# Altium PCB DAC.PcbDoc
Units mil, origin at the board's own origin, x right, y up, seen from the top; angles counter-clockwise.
Board outline 6520 x 6780 mil, 2 copper layers (Top Layer, Bottom Layer); 122 components, 76 nets, 405 pads, 94 vias.
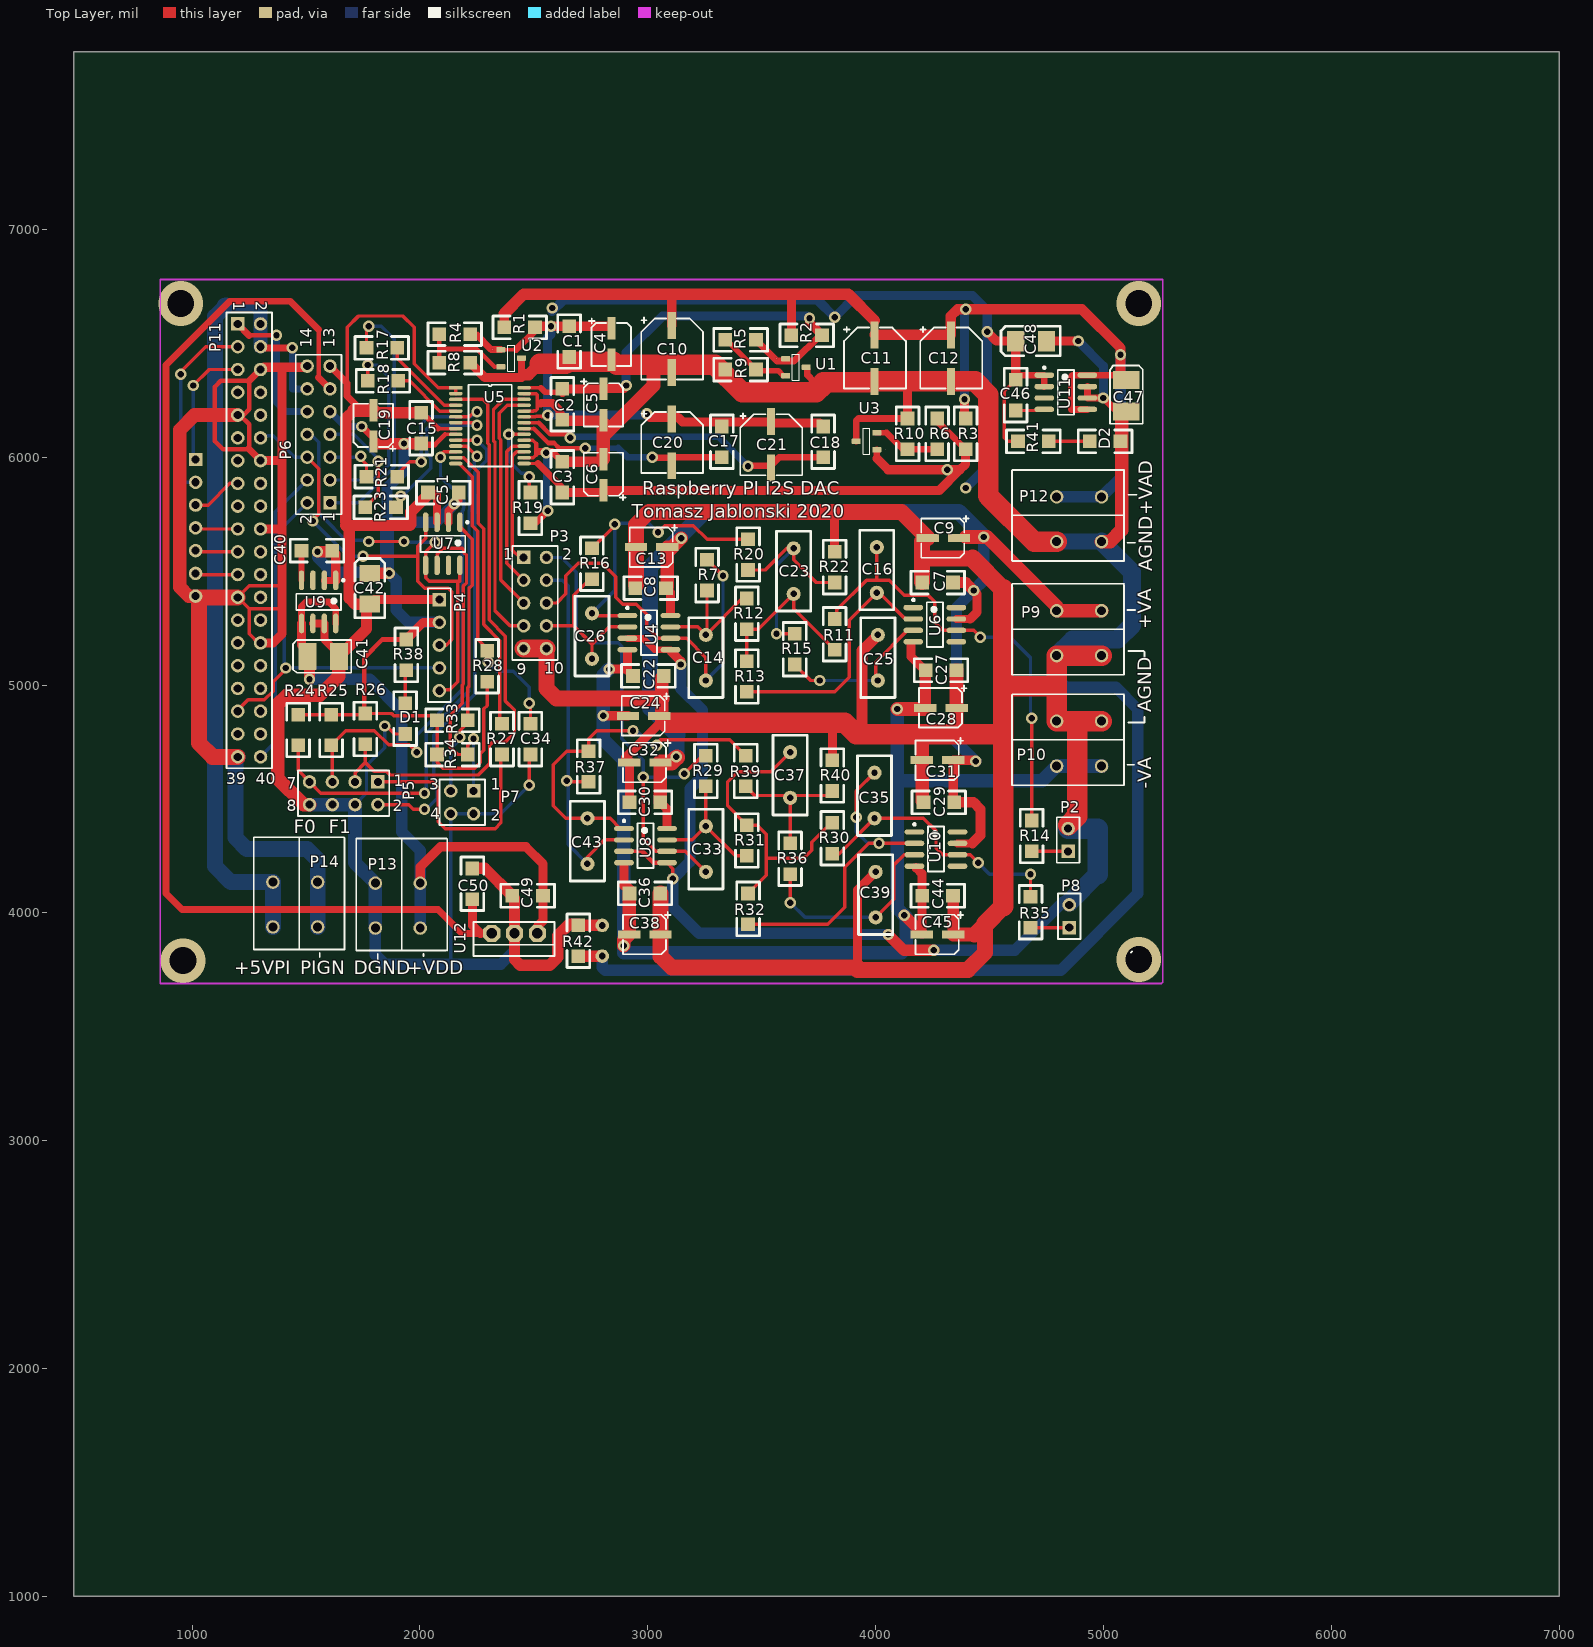
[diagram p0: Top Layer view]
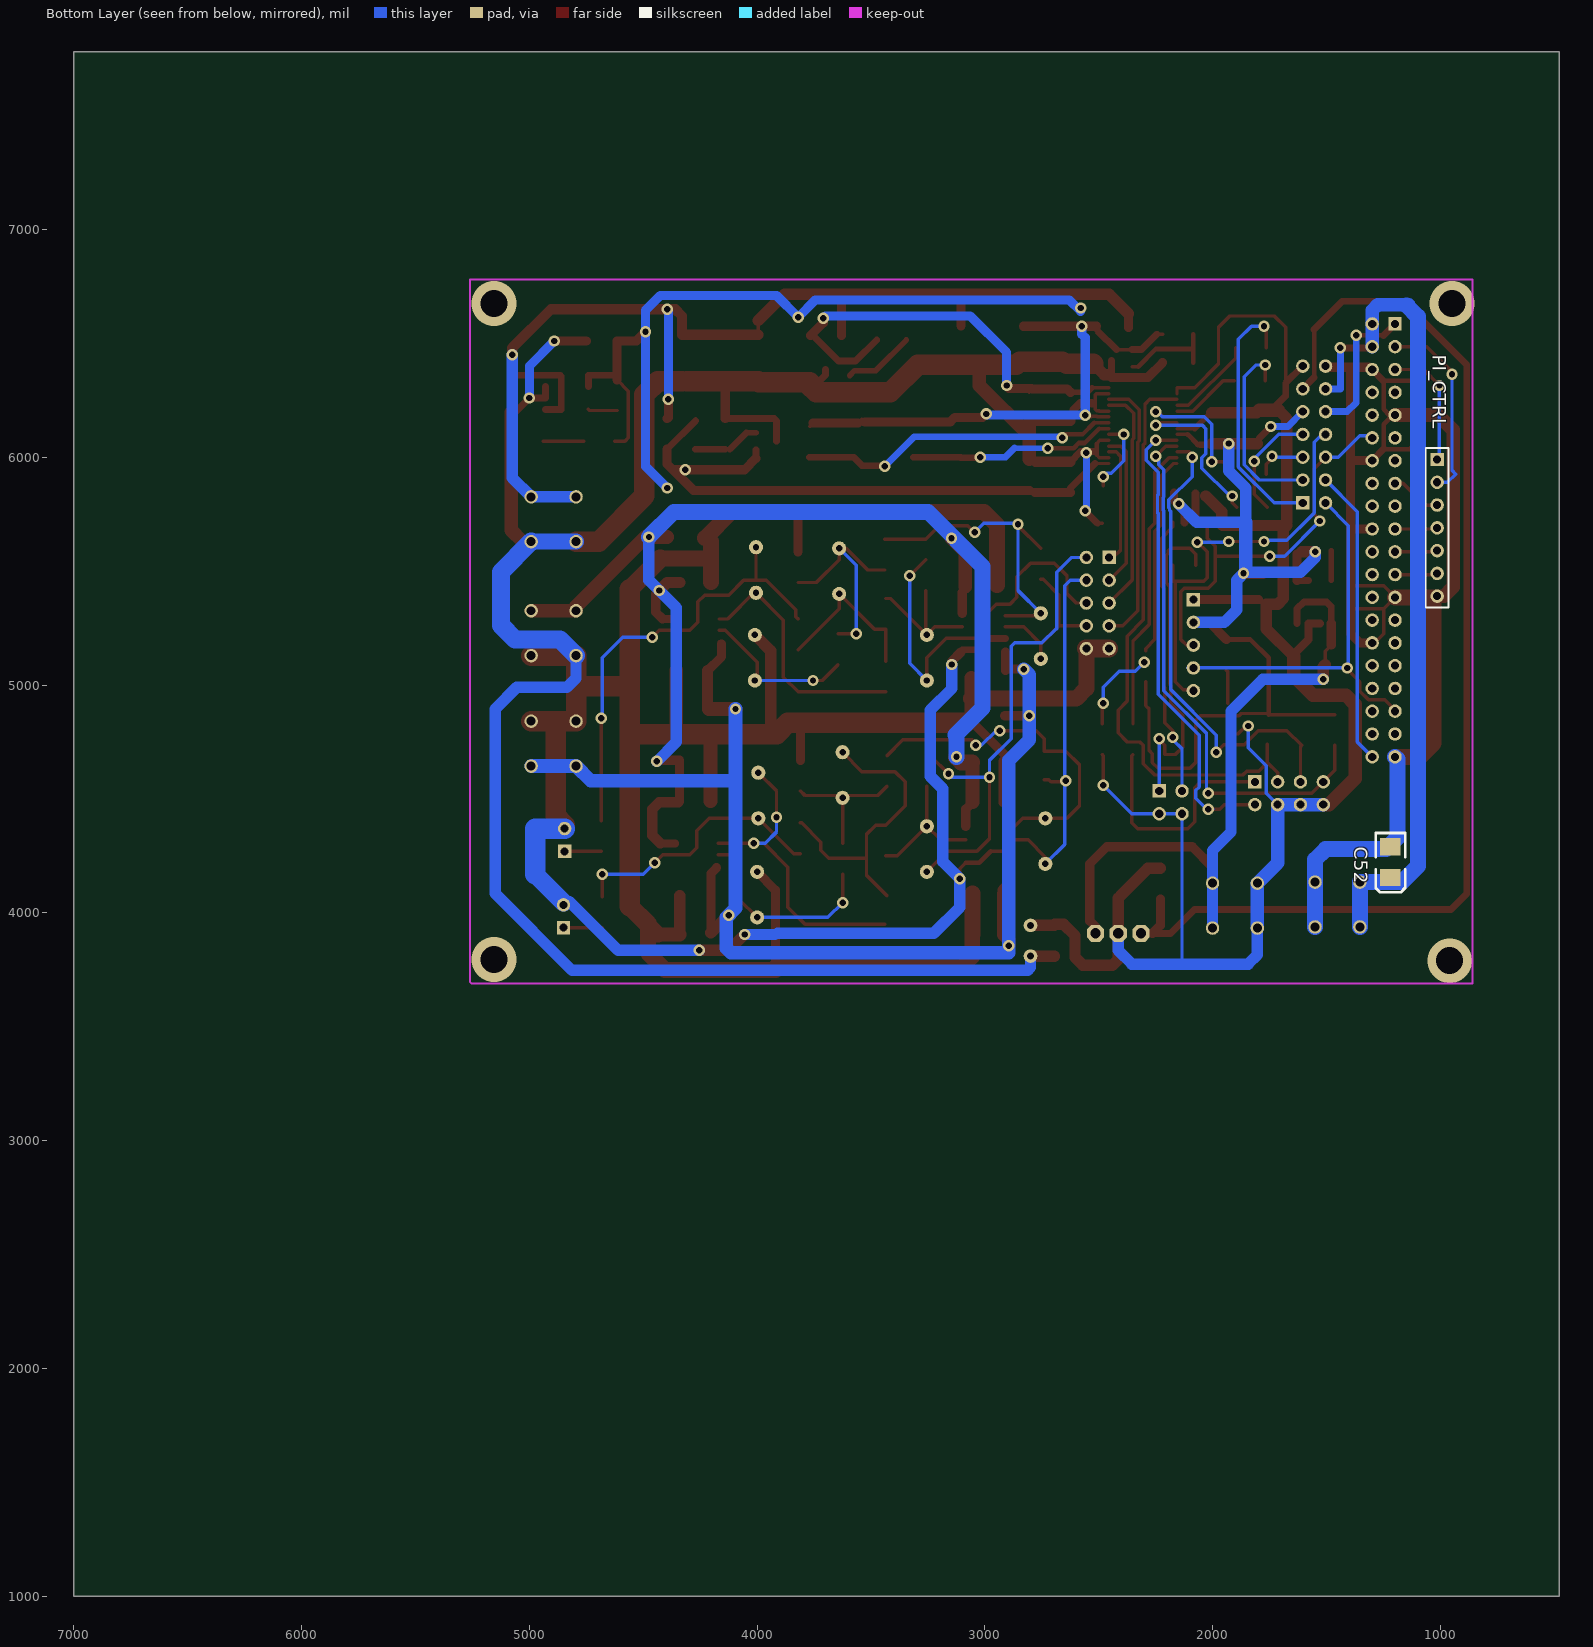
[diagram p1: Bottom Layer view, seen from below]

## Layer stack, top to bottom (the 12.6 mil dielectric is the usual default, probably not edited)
Top Solder: solder mask 0.4, Solder Resist, Dk 3.5
Top Layer: signal copper 1.4
Dielectric 1: dielectric 12.6, FR-4, Dk 4.8
Bottom Layer: signal copper 1.4
Bottom Solder: solder mask 0.4, Solder Resist, Dk 3.5

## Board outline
480,1000 7000,1000 7000,7780 480,7780

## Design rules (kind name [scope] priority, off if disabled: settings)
Clearance [All] p1: gap=10 ignorepadtopadclearanceinfootprint=FALSE except(0: Arc-Hole Track-Hole SMDPad-Hole THPad-Hole Via-Hole Fill-Hole Poly-Hole Region-Hole Text-Hole)
PolygonConnect [All] p1: connectstyle=Relief reliefconductorwidth=10 reliefentries=4 polygonreliefangle="90 Angle" airgapwidth=10
RoutingVias [All] p1: holewidth=28 width=50 viastyle="Through Hole" minholewidth=28 minwidth=50 maxholewidth=28 maxwidth=50
SolderMaskExpansion [All] p1: expansion=4
Width Width_2 [All] p1: maxlimit=15 minlimit=15 preferedwidth=15
Width Width_1 [InNet('PIGND')] p2: maxlimit=80 minlimit=60 preferedwidth=70
Width [InNet('+5VPI')] p3: maxlimit=30 minlimit=30 preferedwidth=30
30 further rules are at their usual default settings.

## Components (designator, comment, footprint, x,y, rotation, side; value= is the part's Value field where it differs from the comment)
C1 "" 1206 2655,6575 r270 top
C2 "" 1206 2625,6300 r270 top
C3 "" 1206 2625,5845 r90 top
C4 "" 10uf/25v 2840,6495 r90 top
C5 "" 10uf/25v 2805,6230 r90 top
C6 "" 10uf/25v 2805,5925 r270 top
C7 "" 1206 4340,5450 r180 top
C8 "" 1206 3080,5425 r180 top
C9 "" 10uf/25v 4295,5645 r0 top
C10 "47u" 47u/25v 3105,6475 r90 top
C11 "47u" 47u/25v 3995,6435 r90 top
C12 "47u" 47u/25v 4330,6435 r90 top
C13 "" 10uf/25v 3015,5605 r0 top
C14 "" RAD0.2 3255,5020 r90 top
C15 "" 1206 2005,6060 r90 top
C16 "" RAD0.2 4005,5405 r90 top
C17 "" 1206 3325,6135 r270 top
C18 "" 1206 3770,6135 r270 top
C19 "" 10uf/25v 1795,6140 r270 top
C20 "47u" 47u/25v 3105,6065 r90 top
C21 "47u" 47u/25v 3540,6055 r90 top
C22 "" 1206 2935,5040 r0 top
C23 "" RAD0.2 3640,5400 r90 top
C24 "" 10uf/25v 2980,4865 r0 top
C25 "" RAD0.2 4010,5020 r90 top
C26 "" RAD0.2 2755,5115 r90 top
C27 "" 1206 4220,5065 r0 top
C28 "" 10uf/25v 4285,4900 r0 top
C29 "" 1206 4345,4485 r180 top
C30 "" 1206 3055,4485 r180 top
C31 "" 10uf/25v 4270,4670 r0 top
C32 "" 10uf/25v 2985,4660 r0 top
C33 "" RAD0.2 3255,4180 r90 top
C34 "" 1206 2485,4830 r270 top
C35 "" RAD0.2 3995,4615 r270 top
C36 "" 1206 2920,4085 r0 top
C37 "" RAD0.2 3625,4705 r270 top
C38 "" 10uf/25v 2985,3905 r0 top
C39 "" RAD0.2 4000,3980 r90 top
C40 "10n" 1206 1615,5590 r180 top
C41 "1uF" 10uSMD 1575,5125 r180 top
C42 "10uF" 3528 1780,5490 r90 top
C43 "" RAD0.2 2735,4215 r90 top
C44 "" 1206 4205,4075 r0 top
C45 "" 10uf/25v 4270,3905 r0 top
C46 "10n" 1206 4615,6340 r270 top
C47 "1uF" 10uSMD 5100,6270 r90 top
C48 "1uF" 3528 4615,6510 r180 top
C49 "" 1206 2540,4075 r180 top
C50 "" 1206 2230,4060 r90 top
C51 "" 1206 2170,5845 r180 top
C52 "10uF" 3528 1220,4155 r270 bottom
D1 "LED0" 1206 1935,4920 r270 top
D2 "LED0" 1206 4940,6070 r0 top
P2 "CH_L" HDR1X2 4845,4270 r90 top
P3 "FLT_ANALOG" HDR2X5 2455,5560 r270 top
P4 "MCLK_MUL" HDR1X5 2085,5375 r270 top
P5 "Header 4X2" HDR2X4 1815,4575 r180 top
P6 "I2S_ISOL" HDR2X7 1605,5800 r90 top
P7 "MCLK SET" HDR2X2 2235,4535 r180 top
P8 "CH_R" HDR1X2 4850,3935 r90 top
P9 "" wago 4795,5145 r0 top
P10 "" wago 4795,4660 r0 top
P11 "PI_connect" HDR2X20 1200,6585 r270 top
P12 "" wago 4795,5645 r0 top
P13 "" wago 1820,4130 r270 top
P14 "" wago 1370,4135 r270 top
PI_CTRL "" HDR1X7 1015,5990 r270 bottom
R1 "" 1206 2370,6570 r0 top
R2 "" 1206 3630,6535 r0 top
R3 "" 1206 4395,6170 r270 top
R4 "" 1206 2220,6540 r180 top
R5 "" 1206 3475,6515 r180 top
R6 "" 1206 4270,6170 r270 top
R7 "" 1206 3260,5415 r90 top
R8 "" 1206 2085,6415 r0 top
R9 "" 1206 3475,6385 r180 top
R10 "" 1206 4140,6035 r90 top
R11 "" 1206 3820,5290 r270 top
R12 "" 1206 3435,5245 r90 top
R13 "" 1206 3435,4970 r90 top
R14 "" 1206 4685,4270 r90 top
R15 "" 1206 3645,5090 r90 top
R16 "" 1206 2755,5600 r270 top
R17 "" 1206 1765,6480 r0 top
R18 "" 1206 1770,6335 r0 top
R19 "" 1206 2485,5710 r90 top
R20 "" 1206 3440,5505 r90 top
R21 "" 1206 1765,5915 r0 top
R22 "" 1206 3820,5585 r270 top
R23 "" 1206 1760,5780 r0 top
R24 "" 1206 1465,4870 r270 top
R25 "" 1206 1610,4870 r270 top
R26 "" 1206 1760,4875 r270 top
R27 "" 1206 2360,4830 r270 top
R28 "" 1206 2295,5015 r90 top
R29 "" 1206 3255,4555 r90 top
R30 "" 1206 3810,4260 r90 top
R31 "" 1206 3435,4385 r270 top
R32 "" 1206 3440,3950 r90 top
R33 "" 1206 2075,4845 r0 top
R34 "" 1206 2075,4695 r0 top
R35 "" 1206 4680,3935 r90 top
R36 "" 1206 3625,4170 r90 top
R37 "" 1206 2740,4710 r270 top
R38 "" 1206 1940,5200 r270 top
R39 "" 1206 3430,4555 r90 top
R40 "" 1206 3810,4670 r270 top
R41 "" 1206 4625,6070 r0 top
R42 "" 1206 2695,3810 r90 top
U1 "TL431" SOT23-3 3650,6395 r0 top
U2 "TL431" SOT23-3 2400,6435 r0 top
U3 "TL431" SOt23-3 3960,6070 r180 top
U4 "OPA1612AID" TI-D8_N 3005,5230 r0 top
U5 "PCM1794A" pcm1796 2150,6305 r0 top
U6 "OPA1611AID" TI-D8_N 4260,5265 r0 top
U7 "ICS570B" TI-D8_n 2100,5620 r270 top
U8 "OPA1612AID" TI-D8_N 2990,4295 r0 top
U9 "3V3" TI-D8_N 1555,5365 r270 top
U10 "OPA1611AID" TI-D8_N 4265,4280 r0 top
U11 "5V0" TI-D8_n 4835,6285 r0 top
U12 "7805" 78XXST 2490,3895 r180 top

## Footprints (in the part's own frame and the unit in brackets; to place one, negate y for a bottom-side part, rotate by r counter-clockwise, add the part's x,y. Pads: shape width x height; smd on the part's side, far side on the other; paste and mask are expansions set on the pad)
10uf/25v [mm]
  rect 2.5x0.9 smd: 1(1.8,0) 2(-1.7,0)
  silkscreen extent -2.4,-2.2 2.9,2.5
10uSMD [mm]
  rect 2x3 smd: 1(1.75,0) 2(-1.75,0)
  silkscreen extent -3.12,-1.85 3.35,1.8
47u/25v [mm]
  rect 3x0.9 smd: 1(2.6,0) 2(-2.6,0)
  silkscreen extent -3.4,-3.5 3.5,3.4
78XXST [mil]
  oct 75x75 hole 45: 1(-25,-15) 2(75,-15) 3(175,-15)
  silkscreen extent -100,-65 255,85
1206 [mil]
  rect 60x60 smd: 1(0,0) 2(135,0)
  silkscreen extent -50,-50 185,50
3528 [mil]
  rect 75x90 smd: 1(0,0) 2(-135,0)
  silkscreen extent -195,-65 65,65
HDR1X2 [mm] "Connector; Header; 2 Position"
  rect 1.5x1.5 hole 0.9: 1(0,0)
  round 1.5 hole 0.9: 2(2.54,0)
  silkscreen extent -1.27,-1.27 3.81,1.27
HDR1X5 [mm] "Connector; Header; 5 Position"
  rect 1.5x1.5 hole 0.9: 1(0,0)
  round 1.5 hole 0.9: 2(2.54,0) 3(5.08,0) 4(7.62,0) 5(10.16,0)
  silkscreen extent -1.27,-1.27 11.43,1.27
HDR1X7 [mm] "Connector; Header; 7 Position"
  rect 1.5x1.5 hole 0.9: 1(0,0)
  round 1.5 hole 0.9: 2(2.54,0) 3(5.08,0) 4(7.62,0) 5(10.16,0) 6(12.7,0) 7(15.24,0)
  silkscreen extent -1.27,-1.27 16.51,1.27
HDR2X2 [mm] "Connector; Header; 2x2 Position"
  rect 1.5x1.5 hole 0.9: 1(0,0)
  round 1.5 hole 0.9: 2(0,2.54) 3(2.54,0) 4(2.54,2.54)
  silkscreen extent -1.27,-1.27 3.81,3.81
HDR2X4 [mm] "Connector; Header; 4x2 Position"
  rect 1.5x1.5 hole 0.9: 1(0,0)
  round 1.5 hole 0.9: 2(0,2.54) 3(2.54,0) 4(2.54,2.54) 5(5.08,0) 6(5.08,2.54) 7(7.62,0) 8(7.62,2.54)
  silkscreen extent -1.27,-1.27 8.89,3.81
HDR2X5 [mm] "Connector; Header; 5x2 Position"
  rect 1.5x1.5 hole 0.9: 1(0,0)
  round 1.5 hole 0.9: 2(0,2.54) 3(2.54,0) 4(2.54,2.54) 5(5.08,0) 6(5.08,2.54) 7(7.62,0) 8(7.62,2.54) 9(10.16,0) 10(10.16,2.54)
  silkscreen extent -1.27,-1.27 11.43,3.81
HDR2X7 [mm] "Connector; Header; 7x2 Position"
  rect 1.5x1.5 hole 0.9: 1(0,0)
  round 1.5 hole 0.9: 2(0,2.54) 3(2.54,0) 4(2.54,2.54) 5(5.08,0) 6(5.08,2.54) 7(7.62,0) 8(7.62,2.54) 9(10.16,0) 10(10.16,2.54) 11(12.7,0) 12(12.7,2.54) 13(15.24,0) 14(15.24,2.54)
  silkscreen extent -1.27,-1.27 16.51,3.81
HDR2X20 [mm] "Connector; Header; 20x2 Position"
  rect 1.5x1.5 hole 0.9: 1(0,0)
  round 1.5 hole 0.9: 2(0,2.54) 3(2.54,0) 4(2.54,2.54) 5(5.08,0) 6(5.08,2.54) 7(7.62,0) 8(7.62,2.54) 9(10.16,0) 10(10.16,2.54) 11(12.7,0) 12(12.7,2.54) 13(15.24,0) 14(15.24,2.54) 15(17.78,0) 16(17.78,2.54) 17(20.32,0) 18(20.32,2.54) 19(22.86,0) 20(22.86,2.54) 21(25.4,0) 22(25.4,2.54) 23(27.94,0) 24(27.94,2.54) 25(30.48,0) 26(30.48,2.54) 27(33.02,0) 28(33.02,2.54) 29(35.56,0) 30(35.56,2.54) 31(38.1,0) 32(38.1,2.54) 33(40.64,0) 34(40.64,2.54) 35(43.18,0) 36(43.18,2.54) 37(45.72,0) 38(45.72,2.54) 39(48.26,0) 40(48.26,2.54)
  silkscreen extent -1.27,-1.27 49.53,3.81
pcm1796 [mm]
  rect 1.5x0.4 smd: 1(0.178,0)
  oval 1.5x0.4 smd: 2(0.178,-0.65) 3(0.178,-1.3) 4(0.178,-1.95) 5(0.178,-2.6) 6(0.178,-3.25) 7(0.178,-3.9) 8(0.178,-4.55) 9(0.178,-5.2) 10(0.178,-5.85) 11(0.178,-6.5) 12(0.178,-7.15) 13(0.178,-7.8) 14(0.178,-8.45) 15(7.797,-8.45) 16(7.797,-7.8) 17(7.797,-7.15) 18(7.797,-6.5) 19(7.797,-5.85) 20(7.797,-5.2) 21(7.797,-4.55) 22(7.797,-3.9) 23(7.797,-3.25) 24(7.797,-2.6) 25(7.797,-1.95) 26(7.797,-1.3) 27(7.797,-0.65) 28(7.797,0)
  silkscreen extent 1.58,-8.78 6.41,0.32
RAD0.2 [mil]
  round 62 hole 28: 1(0,0) 2(200,0)
  silkscreen extent -75,-75 275,75
SOT23-3 [mm] "SOT23, 3 pin"
  round 0.5 on Mech15: 0(0,0)
  rrect25% 1x0.6 smd: 1(-1.15,0.95) 2(-1.15,-0.95) 3(1.15,0)
  silkscreen extent -0.38,-1.45 0.38,1.45, body extent -1.4,-1.45 1.4,1.45, height 1.29
SOt23-3 [mm] "SOT23, 3 pin"
  round 0.5 on Mech15: 0(0,0)
  rrect25% 1x0.6 smd: 1(-1.15,0.95) 2(-1.15,-0.95) 3(1.15,0)
  silkscreen extent -0.38,-1.45 0.38,1.45, body extent -1.4,-1.45 1.4,1.45, height 1.29
TI-D8_N [mm] "SOIC, 8-Leads, Body 4.9x3.9mm, Pitch 1.27mm, IPC Medium Density"
  oval 2.2x0.6 smd: 1(-2.4,1.905) 2(-2.4,0.635) 3(-2.4,-0.635) 4(-2.4,-1.905) 5(2.4,-1.905) 6(2.4,-0.635) 7(2.4,0.635) 8(2.4,1.905)
  silkscreen extent -2.52,-2.5 0.9,2.88, body extent -2,-2.5 2,2.5, height 1.75
TI-D8_n [mm] "SOIC, 8-Leads, Body 5x4mm, Pitch 1.27mm, IPC Medium Density"
  oval 2.2x0.6 smd: 1(-2.4,1.905) 2(-2.4,0.635) 3(-2.4,-0.635) 4(-2.4,-1.905) 5(2.4,-1.905) 6(2.4,-0.635) 7(2.4,0.635) 8(2.4,1.905)
  silkscreen extent -2.52,-2.5 0.9,2.88, body extent -2,-2.5 2,2.5, height 1.75
wago [mm]
  round 1.5 hole 1: 1(0,4.6) 1(5,4.6) 2(0,-0.4) 2(5,-0.4)
  silkscreen extent -5,-2.54 7.5,7.6

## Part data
C1 C2 C3 C7 C8 C14 C15 C16 C17 C18 C22 C23 C25 C26 C27 C29 C30 C33 C34 C35 C36 C37 C39 C43 C44 C49 C50 C51: library part Cap, "Capacitor"
C4 C5 C6 C9 C10 C11 C12 C13 C19 C20 C21 C24 C28 C31 C32 C38 C41 C42 C45 C47 C48 C52: library part ELECTRO2, "Electrolytic Capacitor"
C40 C46: library part CAP, "Capacitor"
D1 D2: "Typical INFRARED GaAs LED"
P2 P8 P9 P10 P12 P13 P14: library part "Header 2", "Header, 2-Pin"
P3: library part "Header 5X2", "Header, 5-Pin, Dual row"
P4: library part "Header 5", "Header, 5-Pin"
P5: "Header, 4-Pin, Dual row"
P6: library part "Header 7X2", "Header, 7-Pin, Dual row"
P7: library part "Header 2X2", "Header, 2-Pin, Dual row"
P11: library part "Header 20X2", "Header, 20-Pin, Dual row"
PI_CTRL: library part "Header 7", "Header, 7-Pin"
R1 R2 R3 R4 R5 R6 R7 R8 R9 R10 R11 R12 R13 R14 R15 R16 R17 R18 R19 R20 R21 R22 R23 R24 R25 R26 R27 R28 R29 R30 R31 R32 R33 R34 R35 R36 R37 R38 R39 R40 R41 R42: library part Res2, "Resistor"
U4 U6 U8 U10: "1.1 nV/rtHz Noise, Low Power, Precision Operational Amplifier, 4.5 to 36 V, -40 to 85 degC, 8-pin SOIC (D8), Green (RoHS & no Sb/Br)"
U7: library part ICS570
U9 U11: library part LT1763
U12: library part 78XX

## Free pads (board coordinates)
  round 60 hole 30: 0(2800,3945) 1(2800,3810)

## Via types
v1: diameter 50, hole 28, Top Layer to Bottom Layer, 90 vias
v2: diameter 196.85, hole 118.11, Top Layer to Bottom Layer, 4 vias

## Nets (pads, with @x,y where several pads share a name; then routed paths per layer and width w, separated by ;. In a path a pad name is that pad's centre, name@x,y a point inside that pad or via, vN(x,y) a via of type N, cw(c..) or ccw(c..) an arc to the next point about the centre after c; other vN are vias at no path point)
+3,3VDD: C15.1 C19.1 C40.1 C42.1 C51.1 P4.2 P6.9 R24.1 R25.1 R26.1 R28.1 R33.1 R34.1 R38.1 U5.9 U7.2 U9.1 U9.2 | length 4840.4
  Top Layer w15: R24.1 R25.1 1755,4870 R26.1 1875,4875 1885,4865 2055,4865 R33.1 R34.1 2075,4660 2100,4635 2240,4635 2264.82,4659.82 2264.82,4699.29 2280,4714.47 2280,4895 2295,4910 R28.1 ; v1@1550,5570 v1(1550,5585) ; C40.1@1610,5585 C40.1 C40.1@1630,5575 ; C19.1@1795,6085 C19.1 C19.1@1804.13,6060 ; C15.1 C15.1@2010,6055 ; 2110.28,6100.27 U5.9
  Top Layer w20: R26.1@1755,4870 1755,5120 1835,5200 R38.1
  Top Layer w22: 2065,6055 2110.28,6100.27
  Top Layer w25: 2055,6055 2065,6055
  Top Layer w30: U9.2 U9.1 ; v1(1745,6135) C19.1@1795,6085 ; C15.1@2010,6055 2055,6055
  Top Layer w35: U7.2 2125,5765 2170,5810 C51.1
  Top Layer w40: U9.1 C40.1@1630,5575 ; R38.1 2015,5275 P4.2
  Top Layer w50: v1(1550,5585) C40.1@1610,5585 ; C42.1 v1(1865,5490) ; C19.1@1804.13,6060 v1(1930,6060) C15.1
  Bottom Layer w30: P6.9 1670,6135 v1(1745,6135)
  Bottom Layer w50: v1(1550,5585) 1550,5560 1615,5495 v1@1845,5495 ; v1@1855,5500 1895,5460 1895,5330 1950,5275 P4.2 ; v1(1930,6060) 1930,5939.44 1855,5864.44 1855,5715 2070,5715 v1(2150,5795)
  Bottom Layer w60: v1@1855,5500 1855,5715
+3,3VPI: P6.10 P11.1 | length 637.3
  Top Layer w20: 1250,6535 v1(1370,6535)
  Top Layer w30: P11.1 1250,6535
  Bottom Layer w30: v1(1370,6535) 1370,6275 1370,6240 1410,6200 P6.10
+5VA: C46.1 C48.1 R41.1 U11.1 U11.2 | length 3684.7
  Top Layer w15: R41.1 4580,6070 4565,6085 4565,6290 C46.1 C46.1@4635,6360
  Top Layer w30: C46.1@4635,6360 U11.1 U11.2
  Top Layer w40: v1(4490,6550) 4530,6510 C48.1 C46.1
  Bottom Layer w40: v1@2580,6640 2630,6690 3745,6690 v1(3820,6615) 3915,6710 4425,6710 4490,6645 v1(4490,6550) 4490,5960 v1(4395,5865)
  other v1: 2580,6655
+5VDD: C50.1 P6.11 U12.3 | length 5105.5
  Top Layer w15: 2265,3910 U12.3
  Top Layer w20: 1555,6350 1555,6560
  Top Layer w30: 1555,6350 P6.11 ; 1555,6560 1430,6685 1165,6685 885,6405 885,4085 955,4015 2080,4015 2185,3910 2265,3910
  Top Layer w40: C50.1 2230,3945 2265,3910
+5VPI: C52.1 P6.12 P11.2 P11.4 P14.2 | length 3676.8
  Top Layer w30: P11.4@1300,6480 v1(1440,6480)
  Bottom Layer w30: v1(1440,6480) 1440,6300 P6.12
  Bottom Layer w60: 1140,6670 1275,6670 1300,6645 P11.2 P11.4
  Bottom Layer w70: 1148.92,6666.08 1100,6617.17 1100,4205 1170,4135 1354.25,4135 P14.2@1354.25,3938.15
+VA: C7.1 C8.1 C9.1 C13.1 C29.1 C30.1 C31.1 C32.1 P9.1 U4.8 U6.7 U8.8 U10.7 | length 6044.1
  Top Layer w15: C32.1@3055,4659.13 C32.1 ; C8.1@3085.87,5430.87 C8.1 C8.1@3099.49,5405.51 ; C29.1@4340.87,4489.13 C29.1 ; v1@4435,4670 v1(4440,4665) ; P9.1@4795,5326.1 P9.1@4795,5345
  Top Layer w35: U6.7 4415,5290 ; U10.7 4425,4305
  Top Layer w40: C30.1 3084.49,4455.51 U8.8@3084.49,4380 ; U4.8@3099.49,5315 C8.1@3099.49,5405.51 ; C29.1@4340.87,4489.13 C31.1 v1@4435,4670 ; 4415,5290 4445,5320 4445,5400 v1(4430,5415)
  Top Layer w45: C29.1 4430,4485 4460,4455 4460,4340 4425,4305
  Top Layer w50: C7.1 4395,5450 v1(4430,5415)
  Top Layer w60: C30.1 C32.1@3055,4659.13 ; C8.1@3085.87,5430.87 C13.1 3085.87,5583.99 v1(3146.88,5645) ; C9.1@4395,5650 v1(4475,5650) 4490,5650 P9.1@4795,5345 ; P9.1@4795,5326.1 P9.1@4991.85,5326.1
  Top Layer w70: C32.1 3105,4660 v1@3127.5,4682.5
  Bottom Layer w50: v1(4440,4665) 4355,4750 4355,5340 v1(4430,5415) 4475,5460 v1(4475,5650)
  Bottom Layer w70: v1(3125,4685) 3125,4775 3130,4780 3010,4900 3010,5520 3250,5760 4365,5760 v1(4475,5650)
+VADAC: C10.1 C11.1 C12.1 C47.1 P12.1 R1.1 R2.1 R3.1 U11.5 U11.8 | length 5328.5
  Top Layer w15: C11.1 3995,6600 ; C47.1@5050,6360 5071.1,6338.9 5085,6338.9 C47.1@5075,6348.9
  Top Layer w30: U11.5 4860,6210 4860,6355 4865,6360 U11.8 C47.1@5050,6360
  Top Layer w40: R1.1 2370,6630 ; C10.1 3105,6715 ; R2.1 3630,6715 ; v1(4390,6255) 4390,6175 R3.1
  Top Layer w45: C11.1 C12.1 4330,6620 4360,6650 v1(4395,6650) 4905,6650 5075,6480 v1(5075,6450) C47.1@5075,6348.9
  Top Layer w50: 2370,6630 2455,6715 3105,6715 3630,6715 3880,6715 3995,6600
  Bottom Layer w40: v1(4390,6255) 4390,6645 v1(4395,6650)
  Bottom Layer w50: P12.1@4795,5826.1 4991.85,5826.1 5075,5909.25 v1(5075,6450)
+VCC1: C1.1 C4.1 C17.1 C18.1 C20.1 C21.1 R1.2 R4.1 U2.1 U5.23 | length 2437.3
  Top Layer w15: R4.1 R4.1@2245,6540 ; U2.1 2422.4,6472.4 ; U5.23 2507.19,6177.05 2509.1,6178.96 2531.88,6178.96 2533.79,6177.05 2552.05,6177.05 v1(2560,6185) ; R1.2 R1.2@2510,6575 ; C4.1@2830.87,6575 C4.1 ; v1(2995,6190) v1@3010,6175 ; C21.1@3527.64,6155 3540,6167.36 C21.1@3557.36,6150 ; C18.1@3755,6150 C18.1
  Top Layer w30: R4.1@2245,6540 2312.6,6472.4 U2.1 ; 2422.4,6472.4 R1.2@2505,6555
  Top Layer w40: R1.2@2510,6575 v1(2575,6575) C1.1 C4.1@2830.87,6575 ; v1@3010,6175 3132.36,6175 3152.36,6155 C21.1@3527.64,6155 ; C21.1@3557.36,6150 C18.1@3755,6150
  Bottom Layer w15: v1@2990,6185 v1(2995,6190)
  Bottom Layer w40: v1(2575,6575) 2575,6540 2560,6525 v1(2560,6185) v1@2990,6185
+VCC2L: C2.1 C5.1 R2.2 R5.1 U1.1 U5.28 | length 1948.7
  Top Layer w15: U5.28 2530,6305 ; C5.1@2790.87,6300 C5.1@2805,6285.87 ; R5.1@3470,6520 R5.1
  Top Layer w25: 2530,6305 2550,6285 C2.1@2625,6285
  Top Layer w30: R5.1 3567.6,6422.4 3642.4,6422.4 3755,6535 R2.2
  Top Layer w40: C2.1@2625,6285 2640,6300 C5.1@2790.87,6300 ; C5.1@2795,6300.87 v1@2895,6300.87 ; v1@3710,6590 R2.2
  Bottom Layer w40: v1(2905,6315) 2905,6460 3065,6620 3700,6620 v1(3710,6610)
+VCC2R: C3.1 C6.1 R3.2 R6.1 U3.1 U5.15 | length 2714.2
  Top Layer w15: U5.15 2517.68,5972.32 ; C3.1 C3.1@2625,5865 ; 2780.87,5845 C6.1@2790,5854.13 ; R6.1@4270,6160 R6.1
  Top Layer w30: 2517.68,5972.32 C3.1@2625,5865 ; 4005.28,5994.72 U3.1 ; R6.1@4270,6160 R3.2
  Top Layer w40: C3.1 2780.87,5845 ; C6.1 4279.13,5854.13 4370,5945 ; 4005.28,5994.72 4055,5945 4370,5945 ; R3.2 4395,5970 4370,5945
  other v1: 4315,5945
+VDDAC: C41.1 C49.1 P13.1 U9.5 U9.8 U12.1 | length 3011.4
  Top Layer w15: C41.1@1480,5175 1506.1,5148.9 C41.1 C41.1@1506.1,5088.9 ; U12.1 U12.1@2515,3940
  Top Layer w30: U9.5 1480,5345 1500,5365 1600,5365 1630,5335 U9.8
  Top Layer w40: C41.1@1480,5175 U9.5 ; P13.1@2001.1,4130 2001.1,4201.1 2090,4290 2465,4290 2540,4215 C49.1 2540,3965 U12.1@2515,3940
  Top Layer w50: C41.1@1506.1,5088.9 1515,5080 v1(1515,5025)
  Bottom Layer w50: v1(1515,5025) 1780,5025 1920,4885 1920,4355 2001.1,4273.9 2001.1,4130 P13.1@2001.1,3933.15
-VA: C22.1 C24.2 C27.1 C28.2 C36.1 C38.2 C44.1 C45.2 P10.2 U4.4 U6.4 U8.4 U10.4 | length 6016.2
  Top Layer w15: 2905,5070 C22.1@2910.51,5064.49 ; C38.2@2915,3901.93 C38.2 ; C36.1@2918.07,4083.07 C36.1 C36.1@2920,4100 ; U6.4@4156.14,5180.63 U6.4 ; C45.2 C45.2@4203.07,3911.93 ; C28.2@4213.07,4895 C28.2
  Top Layer w40: v1(2805,4865) C24.2 ; v1(2830,5070) 2905,5070 ; 2895.51,4124.49 U8.4@2895.51,4210 ; C22.1@2910.51,5064.49 U4.4@2910.51,5145 ; U6.4@4156.14,5180.63 4156.14,5125 C27.1@4218.07,5063.07 ; U10.4@4177.76,4197.76 4203.07,4172.44 C45.2@4203.07,3911.93
  Top Layer w50: 2895.51,4124.49 C36.1@2920,4100 ; v1(4125,3990) C45.2@4203.07,3911.93 ; C28.2 C27.1@4218.07,5063.07
  Top Layer w60: v1(2895,3855) 2895,3881.93 C38.2@2915,3901.93 ; C38.2 C36.1@2918.07,4083.07 ; v1(4095,4895) C28.2@4213.07,4895
  Bottom Layer w60: v1(2830,5070) 2805,5045 2805,4760 2895,4670 2895,3825 4115,3825 4135,3845 4135,3980 4095,4020 v1(4095,4895) ; 4115,4580 4730.75,4580 4795,4644.25 P10.2@4991.85,4644.25
AGND: C1.2 C2.2 C3.2 C4.2 C5.2 C6.2 C7.2 C8.2 C9.2 C10.2 C11.2 C12.2 C13.2 C22.2 C24.1 C25.2 C27.2 C28.1 C29.2 C30.2 C31.2 C32.2 C36.2 C38.1 C39.2 C44.2 C45.1 C47.2 C48.2 D2.2 P2.2 P3.9 P3.10 P8.2 P9.2 P10.1 P12.2 pad.1 R8.2 R9.2 R10.2 R19.1 R22.1 R40.1 R42.1 U1.3 U2.3 U3.3 U4.3 U4.5 U5.16 U5.19 U5.24 U5.27 U8.3 U8.5 U11.6 U11.7 | length 28244
  Top Layer w15: 2445,6350 2445.28,6350.28 ; U5.16 2497.91,5997.91 2510,6010 ; U5.19 2495.32,6074.69 2510,6060 ; U5.24 2497.42,6202.64 2498.74,6203.96 2508.96,6203.96 2515,6210 2515,6275 2510.59,6279.41 U5.27 ; R19.1 R19.1@2505,5710 ; 2510,6030 2515,6025 ; C5.2@2793.07,6160 C5.2@2805,6148.07 ; U8.3 2975,4270 ; 2902.64,4682.64 C32.2@2920,4665.28 ; C38.1@3055,3905.87 C38.1 ; C22.2@3060.87,5030.87 C22.2 ; U8.5 3110,4194.49 v1(3110,4150) ; v1(3145,5090) v1@3145,5105 ; 3730.28,6330 3770,6330 3770,6315 ; 3800,4835 3810,4825 ; 3915,4785 3940,4810 ; C11.2@3992.36,6330 C11.2 ; C7.2@4203.07,5451.93 C7.2 ; C29.2@4205,4490 C29.2 ; C45.1@4340,3905.87 C45.1 ; 4355,4790 4360,4785 ; P2.2 P2.2@4845,4385 ; C47.2@5058.9,6201.1 C47.2@5085,6201.1
  Top Layer w20: 2510,6010 2510,6030 2510,6060 ; 2975,4270 3025,4220 U8.5
  Top Layer w30: 2445,6350 2457.5,6362.5 ; 2445.28,6350.28 U2.3@2445.28,6425 ; R19.1@2505,5710 v1(2560,5765) ; 2515,6025 2580,6025 C3.2 ; U4.3 2980,5205 3030,5155 U4.5 ; U1.3@3700,6385 3700,6360.28 3730.28,6330 ; U3.3 3914.72,6159.72 3925,6170 R10.2 ; U11.7 U11.6 v1(5000,6260) C47.2@5058.9,6201.1
  Top Layer w35: 2530,6235 2532.5,6237.5 2581.75,6237.5 2612.5,6206.75 2612.5,6193.79 2625,6181.29 C2.2@2625,6160
  Top Layer w40: R8.2 2285,6350 2445,6350 ; 2902.64,4682.64 3060.87,4840.87 ; C30.2 C32.2@2920,4665.28 ; U4.5@3105,5145 v1@3145,5105 ; R40.1 3810,4825 ; R22.1 3820,5760 ; 3920,3750 3920,3760 3920,4100 C39.2 ; R10.2 4140,6332.64 ; C48.2 v1(4890,6510)
  Top Layer w45: C3.2 2778.07,5980 ; C2.2@2625,6160 C5.2@2793.07,6160
  Top Layer w50: 2457.5,6362.5 2477.5,6362.5 2525,6410 ; R42.1 pad.1 ; 3940,4810 3940,5150 C25.2 ; v1(4055,3905) 4125,3835 v1(4255,3835) ; C45.1@4340,3905.87 C44.2
  Top Layer w60: C6.2 2805,6095 ; C5.2@2805,6148.07 2805,6095 ; C4.2@2848.07,6420 2863.07,6405 ; 3025,6405 3025,6315 2805,6095 ; 3060.87,4840.87 3060.87,4940 C22.2@3060.87,5030.87 ; C29.2@4205,4490 4205,4785 ; C45.1 4435,3905 ; 4355,4790 C27.2 ; P12.2@4991.85,5629.25 5029.25,5629.25 5080,5680 C47.2@5080,6196.1
  Top Layer w70: P3.10 2555,4985 2600,4940 3060.87,4940 ; C8.2@2948.07,5440 2948.07,5703.07 3005,5760 3820,5760 4113.07,5760 C9.2 ; C38.1@3055,3905.87 C36.2 ; C38.1 3055.87,3809.13 3105,3760 3920,3760 ; 3920,3750 4405,3750 4480,3825 4480,3950 4435,3905 ; C7.2@4203.07,5451.93 C9.2@4203.07,5630 ; 4210,5555 4425,5555
  Top Layer w80: P3.9 P3.10 ; 4425,5555 4560,5420 ; 4480,3950 4560,4030
  Top Layer w90: 2525,6410 C1.2@2640,6410 ; C1.2@2660,6420 C4.2@2848.07,6420 ; 2863.07,6405 3025,6405 3295,6405 3415,6285 3740,6285 3770,6315 ; 3085.87,4835 3800,4835 3865,4835 3915,4785 4205,4785 4360,4785 4540,4785 ; 3770,6330 C11.2@3992.36,6330 ; C11.2 4140,6332.64 4310,6332.64 ; C12.2 4437.36,6332.64 4495,6275 4495,5830 4695.75,5629.25 P12.2@4795,5629.25 ; 4560,4030 4560,4995 ; 4560,5420 4560,4995 ; 4770,4995 4560,4995 ; P2.2@4845,4385 4885,4425 4885,4841.1 ; P10.1@4991.85,4841.1 4885,4841.1 ; P9.2@4991.85,5129.25 4795,5129.25 4795,4841.1 4885,4841.1
  Bottom Layer w30: v1(2555,6020) 2555,5770 v1(2560,5765)
  Bottom Layer w40: v1(4890,6510) 5000,6400 v1(5000,6260)
  Bottom Layer w50: pad.1 2800,3760 2812.5,3747.5 4812.5,3747.5 5150,4085 5150,4895 5055,4990 4835,4990 4795,5030 P9.2@4795,5129.25 ; v1(3145,5090) 3145,4985 3240,4890 3240,4600 3185,4545 3185,4225 v1(3110,4150) 3110,4025 3225,3910 3910,3910 ; 3923,3905 v1(4055,3905) ; v1(4255,3835) 4610,3835 4825,4050 P8.2@4865,4050
  Bottom Layer w70: P12.2@4795,5629.25 P12.2@4991.85,5629.25
  Bottom Layer w80: P9.2@4795,5129.25 4865.75,5200 5062.6,5200 5125,5262.4 5125,5496.1 P12.2@4991.85,5629.25 ; P8.2@4850,4045 4975,4170
  Bottom Layer w90: P2.2 4975,4370 4975,4170
BCK: P6.5 R21.1 | length 231.6
  Top Layer w15: v1(1740,6005) 1735,6000 1765,5970 R21.1@1765,5925
  Bottom Layer w15: P6.5 1735,6000 v1(1740,6005)
BCKPI: P4.3 P6.6 P11.12 U7.4 | length 1807.6
  Top Layer w15: P6.6 1555,5950 1555,5750 v1@1530,5725 ; v1(1750,5565) 1990,5565 ; U7.4 2025,5645 1990,5610 1990,5565 ; P4.3@2070,5175 2115,5175 2140,5200 2140,5410 2125,5425 2020,5425 1990,5455 1990,5565
  Bottom Layer w15: P11.12@1300,6095 1355,6095 1450,6000 P6.6 ; v1(1530,5720) 1685,5565 v1(1750,5565)
DATA: P6.3 R18.1 | length 854.8
  Top Layer w15: R18.1 v1(1770,6405)
  Bottom Layer w15: P6.3 1795.1,5900 1862.5,5967.4 1862.5,6352.5 1810,6405 v1(1770,6405)
DEEM: P5.3 R26.2 U5.3 | length 2625.4
  Top Layer w15: P5.3 1715,4615 1760,4660 ; R26.2 1760,4660 ; U5.3 2276.18,6253.82 2297.5,6232.5 2297.5,6061.69 2304.31,6054.87 2304.31,5285.69 2375,5215 2375,4930 2415,4890 2415,4790 2375,4750 2320,4750 2305.13,4735.13 2305.13,4655.13 2255,4605 1868.8,4605 1851.78,4622.03 1797.97,4622.03 1760,4660
DGND: C15.2 C19.2 C34.2 C41.2 C42.2 C49.2 C50.2 C51.2 D1.2 P4.1 P5.4 P5.6 P5.8 P6.13 P7.2 P7.4 P13.2 pad.0 R42.2 U5.1 U5.2 U5.8 U7.3 U9.6 U9.7 U12.2 | length 9308.7
  Top Layer w15: C41.2 C41.2@1643.9,5136.1 ; 1674.53,5700.47 1674.53,5715.47 ; 1680,6325 1680,6570 1730,6620 1925,6620 1975,6570 1975,6410 2080,6305 U5.1 U5.2 ; C42.2 C42.2@1800,5375 ; C19.2 C19.2@1806.93,6195 ; v1(1845,4820) 1855,4820 1890,4785 D1.2 ; 1955.47,5700.47 1960,5705 ; 2070,5845 2075,5840 ; 2079.13,6125.87 U5.8 ; C49.2 C49.2@2415,4065 ; v1(2480,4560) 2480,4690 C34.2
  Top Layer w25: C15.2@2015,6190 2079.13,6125.87
  Top Layer w30: P6.13 1680,6325 1680,6268.86 1741.93,6206.93
  Top Layer w35: U9.6 U9.7 1580,5200 C41.2@1643.9,5136.1 ; U7.3 2075,5840
  Top Layer w40: C42.2@1800,5375 P4.1
  Top Layer w50: C41.2 1765,5246.1 1765,5355 1715,5355 1690,5380 1690,5685 1674.53,5700.47 1955.47,5700.47 ; 1674.53,5715.47 1674.53,6169.53 1711.93,6206.93 ; C19.2@1806.93,6195 C15.2 ; 1960,5705 1960,5760 C51.2@2030,5830 ; C50.2 2285,4195 C49.2 ; C49.2@2415,4065 U12.2 2415,3795 2440,3770 2570,3770 2605,3805 2605,3900 2655,3950 R42.2@2695,3950 ; R42.2 pad.0
  Top Layer w60: P5.8 1490,4475 1375,4590 1375,4915 1415,4955 1560,4955 1643.9,5038.9 C41.2 ; 1711.93,6206.93 C19.2
  Bottom Layer w15: P5.4 1765,4525 1765,4645 1845,4725 v1(1845,4820) ; 2130,3775 2135,3780 P7.4 P7.2 2355,4435 v1(2480,4560)
  Bottom Layer w50: P13.2@1804.25,3933.15 1804.25,3815.75 1845,3775 2130,3775 2355,3775 2415,3835 U12.2
  Bottom Layer w60: P5.8 P5.6 P5.4 1715,4219.25 1804.25,4130 P13.2@1804.25,3933.15
DOUTPI: P6.4 P11.40 | length 1299.9
  Top Layer w15: P6.4@1495,5910 P6.4
  Bottom Layer w15: P11.40@1310,4695 1365,4750 1365,5760 P6.4
FMT0: P5.7 R24.2 U5.11 | length 2385
  Top Layer w15: R24.2 1465,4625 P5.7 1565,4525 v1(2020,4525) ; U5.11 2205.91,6049.09 v1(2250,6005)
  Bottom Layer w15: v1@2020,4535 2027.5,4542.5 2027.5,4787.5 2215,4975 2215,5764.54 2217.5,5767.04 2217.5,5822.96 2215,5825.46 2215,5945.25 2237.5,5967.75 2237.5,5992.5 v1(2250,6005)
FMT1: P5.5 R25.2 U5.12 | length 2109.3
  Top Layer w15: P5.5 1615,4730 R25.2 1675,4800 1800,4800 1862.5,4737.5 1952.5,4737.5 v1(1985,4705) ; v1(2090,6000) 2090,6010 2103.5,6023.5 U5.12
  Bottom Layer w15: v1(1985,4705) 1985,4780.36 2185,4980.36 2185,5762.4 2190,5767.4 2190,5774.9 2192.5,5777.4 2192.5,5812.6 2090,5915.1 v1(2090,6000)
IOUTL+: P3.5 U5.25 | length 1001.3
  Top Layer w15: P3.5 2455,5360.36 2354.31,5461.04 2354.31,6075.59 2347.5,6082.4 2347.5,6192.5 2383.01,6228.01 2456.74,6228.01 U5.25
IOUTL-: P3.7 U5.26 | length 1191.2
  Top Layer w15: P3.7 2395,5260 2329.31,5325.69 2329.31,6065.23 2322.5,6072.04 2322.5,6207.5 2368.82,6253.82 U5.26
IOUTR+: P3.1 U5.17 | length 535.9
  Top Layer w15: P3.1 2437.01,5560 2405,5592.01 2405,6005 2423.5,6023.5 U5.17
IOUTR-: P3.3 U5.18 | length 683
  Top Layer w15: P3.3 2380,5535 2380,6025 2404.09,6049.09 U5.18
L+: C14.1 P3.6 R7.2 U4.6 | length 1766.2
  Top Layer w15: P3.6 2600,5360 2640,5400 2640,5480 2695,5535 2800,5535 2860,5475 2860,5385 2890,5355 2950,5355 2995,5310 2995,5255 3045,5205 U4.6 3170,5205 3255,5120 C14.1 ; R7.2 v1(3330,5480)
  Bottom Layer w15: C14.1 3330,5095 v1(3330,5480)
L-: C26.1 P3.8 R16.2 U4.2 | length 728.7
  Top Layer w15: P3.8 2675,5260 ; C26.1 2755,5180 ; R16.2 2745,5465 2675,5395 2675,5260 ; U4.2 2830,5255 2755,5180 ; 2675,5260 2755,5180
LRCK: P6.1 R17.1 | length 1143.5
  Top Layer w15: R17.1 1765,6565 v1(1775,6575)
  Bottom Layer w15: P6.1 1730.46,5800 1887.5,5957.04 1887.5,6517.5 1830,6575 v1(1775,6575)
LRCKPI: P4.4 P6.2 P11.35 | length 1813
  Top Layer w15: P11.35@1187.5,4877.5 1245,4935 1316.51,4935 1355,4973.49 1355,5013.49 1410,5068.49 v1(1410,5075)
  Bottom Layer w15: P6.2@1495,5800 P6.2 1405,5700 1405,5075 v1(1410,5075) P4.4 P4.4@2110,5075
MCLK: P6.7 R23.1 | length 493.3
  Top Layer w15: R23.1 1817.5,5837.5 1817.25,5837.75 v1(1817.25,5982.25)
  Bottom Layer w15: P6.7 1710,6100 1817.25,5992.75 v1(1817.25,5982.25)
MCLKPI: P4.5 P6.8 U7.5 U7.8 | length 1828.3
  Top Layer w15: v1(1775,5630) v1(1930,5630) ; v1(2067.5,5627.6) 2067.5,5627.5 2025,5585 U7.5 2025,5470 2040,5455 2175,5455 U7.8 ; P4.5@2110,4980 2130,4980 2165,5015 2165,5455
  Bottom Layer w15: P6.8 1520,6100 1555,6065 1555,5755.1 1572.5,5737.6 1572.5,5737.5 1675,5635 v1@1760,5635 ; v1@1940,5640 1952.4,5627.6 v1(2067.5,5627.6)
MISOIPI: P11.21 PI_CTRL.5 | length 187.1
  Top Layer w15: PI_CTRL.5 1020,5585 P11.21
MOSIPI: P11.19 PI_CTRL.4 | length 187.1
  Top Layer w15: PI_CTRL.4 1020,5685 P11.19
MUTE: P5.2 U5.10 | length 2074.1
  Top Layer w15: P5.2 1950,4475 1970,4455 v1(2020,4455) ; U5.10 2249.68,6074.69 v1(2250,6075)
  Bottom Layer w15: v1@2000,4455 v1(2020,4455) ; v1@2037.5,4465 2075,4502.5 2075,4537.24 2060,4552.24 2060,4780 2240,4960 2240,5754.19 2242.5,5756.69 2242.5,5833.31 2240,5835.81 2240,5934.9 2292.5,5987.4 2292.5,6032.5 v1(2250,6075)
MUTEPI: P11.15 PI_CTRL.3 | length 224.4
  Top Layer w15: PI_CTRL.3 1070,5790 1165,5885 P11.15
NetC14_2: C14.2 R7.1 R12.2 U4.7 | length 606.3
  Top Layer w15: U4.7 3220,5255 C14.2 C14.2@3260,5225 ; R7.1 C14.2@3260,5225 ; R12.2 3415,5380 C14.2@3260,5225
NetC16_1: C16.1 R13.1 U6.2 | length 1104.8
  Top Layer w15: R13.1 3820,4970 3885,5035 3885,5285 C16.1 4015,5405 4130,5290 U6.2
NetC16_2: C16.2 R11.1 R14.2 U6.6 | length 2003.6
  Top Layer w15: R11.1 3830,5300 3830,5330 3960,5460 4005,5460 ; C16.2 4005,5460 ; v1(4460,5210) 4430,5240 U6.6 4295,5240 4260,5275 4260,5365 4230,5395 4125,5395 4060,5460 4005,5460 ; R14.2 v1(4685,4855)
  Bottom Layer w15: v1(4460,5210) 4590,5210 4680,5120 4680,4860 v1(4685,4855)
NetC23_1: C23.1 R11.2 R12.1 R13.2 | length 728.8
  Top Layer w15: R13.2 R12.1 3485,5245 C23.1 3640,5335 R11.2
NetC23_2: C23.2 R15.2 R20.1 R22.2 | length 996.8
  Top Layer w15: R20.1 3515,5505 3610,5600 C23.2 3640,5550 3740,5450 R22.2 ; v1(3565,5225) R15.2
  Bottom Layer w15: v1(3565,5225) 3565,5525 C23.2
NetC25_1: C25.1 R15.1 U6.3 | length 697.5
  Top Layer w15: R15.1 3715,5020 v1(3755,5020) ; C25.1@4000,5020 4000,5100 4140,5240 U6.3
  Bottom Layer w15: v1(3755,5020) C25.1
NetC26_2: C26.2 R16.1 R20.2 U4.1 | length 1381.3
  Top Layer w15: C26.2 2765,5305 U4.1 ; R16.1 2855,5700 v1(2855,5705) ; v1(3045,5670) 3075,5700 3200,5700 3260,5640 R20.2
  Bottom Layer w15: C26.2 2855,5415 2855,5710 3005,5710 v1(3045,5670)
NetC33_2: C33.2 R29.1 R31.2 U8.7 | length 604.2
  Top Layer w15: U8.7 3195,4320 C33.2 ; R29.1 C33.2 ; R31.2 3385,4250 C33.2
NetC35_1: C35.1 R32.1 U10.2 | length 1393.9
  Top Layer w15: R32.1 3790,3950 3865,4025 3865,4200 3970,4305 U10.2 ; v1(3915,4420) 3915,4535 C35.1
  Bottom Layer w15: v1(3915,4420) 3915,4355 3965,4305 v1(4015,4305)
NetC35_2: C35.2 R30.1 R35.2 U10.6 | length 1179.6
  Top Layer w15: R30.1 3840,4260 C35.2 4210,4415 4265,4360 4265,4285 4295,4255 U10.6 4415,4255 v1(4450,4220) ; R35.2 v1(4680,4170)
  Bottom Layer w15: v1(4450,4220) 4500,4170 v1(4680,4170)
NetC37_1: C37.1 R30.2 R31.1 R32.2 | length 1337.6
  Top Layer w15: R32.2@3430,4075 3520,4165 3520,4240 ; C37.1 3540,4620 3395,4620 3350,4575 3350,4470 R31.1 3480,4385 3520,4345 3520,4240 ; R30.2 3805,4395 3720,4310 3720,4275 3685,4240 3520,4240
NetC37_2: C37.2 R36.2 R39.1 R40.2 | length 613.1
  Top Layer w15: R39.1 3470,4515 3615,4515 C37.2 ; R36.2 C37.2 ; R40.2 3790,4515 3635,4515 C37.2
NetC39_1: C39.1 R36.1 U10.3 | length 899.2
  Top Layer w15: v1(3625,4045) R36.1 ; C39.1 4080,4060 4080,4210 4125,4255 U10.3
  Bottom Layer w15: v1(3625,4045) 3690,3980 C39.1
NetC40_2: C40.2 U9.4 | length 130.5
  Top Layer w25: U9.4 C40.2
NetC43_2: C43.2 R37.1 R39.2 U8.1 | length 1560.8
  Top Layer w15: U8.1 2880,4370 2835,4415 C43.2 2640,4415 2585,4470 2585,4650 2645,4710 R37.1 2740,4765 2775,4800 v1(2935,4800) v1@2947.28,4812.28 ; v1(3040,4735) 3055,4750 3055,4760 3360,4760 R39.2
  Bottom Layer w15: v1(2935,4800) 2950.43,4800 3015.43,4735 v1(3040,4735)
NetC46_2: C46.2 U11.4 | length 127.6
  Top Layer w15: C46.2 4735.51,6205 U11.4
NetD1_1: D1.1 R38.2 | length 147.1
  Top Layer w15: D1.1 1935,5060 R38.2
NetD2_1: D2.1 R41.2 | length 180
  Top Layer w15: R41.2 D2.1
NetP2_1: P2.1 R14.1 | length 160
  Top Layer w15: R14.1 P2.1
NetP5_1: P5.1 R27.2 | length 1025.2
  Top Layer w15: P5.1 2055,4575 2080,4550 2080,4400 2110,4370 2330,4370 2355,4395 2355,4690 R27.2@2350,4695
NetP8_1: P8.1 R35.1 | length 170
  Top Layer w15: R35.1 P8.1
NetR4_2: R4.2 R8.1 U2.2 | length 426.8
  Top Layer w15: 2327.05,6397.6 U2.2
  Top Layer w20: R8.1 R4.2 ; 2085,6475 2249.64,6475 2327.05,6397.6
NetR5_2: R5.2 R9.1 U1.2 | length 318.4
  Top Layer w15: R5.2 R5.2@3345,6515 ; R9.1 R9.1@3480,6380
  Top Layer w25: R5.2@3345,6515 R9.1 ; R9.1@3480,6380 3572.32,6380 U1.2@3593.66,6358.66
NetR6_2: R6.2 R10.1 U3.2 | length 294.7
  Top Layer w15: R10.1@4120,6035 R10.1
  Top Layer w25: U3.2 4047.6,6107.4
  Top Layer w30: 4047.6,6107.4 R10.1@4120,6035 ; R10.1 R6.2
NetR17_2: R17.2 U5.4 | length 387.6
  Top Layer w15: R17.2 1900,6435 2106.77,6228.23 U5.4
NetR18_2: R18.2 U5.5 | length 306.8
  Top Layer w15: R18.2 1955,6335 2087.36,6202.64 U5.5
NetR19_2: R19.2 U5.20 | length 341.1
  Top Layer w15: v1(2390,6100) 2390.28,6100.27 U5.20 ; 2480,5875 v1(2480,5915)
  Bottom Layer w15: v1(2390,6100) 2390,5985 2445,5930 2465,5930 v1(2480,5915)
NetR21_2: R21.2 U5.6 | length 651.2
  Top Layer w15: R21.2@1900,5925 1955,5980 v1(2005,5980) ; U5.6 2157.22,6176.83 2216.83,6176.83 2240,6200 v1(2250,6200)
  Bottom Layer w15: v1(2005,5980) 2005,6145 2036.83,6176.83 2221.83,6176.83 v1@2240,6195
NetR23_2: R23.2 U5.7 | length 750.7
  Top Layer w15: R23.2 1915,5800 v1(1915,5830) ; U5.7 2157.22,6151.24 v1@2250.1,6151.24
  Bottom Layer w15: v1(1915,5830) 1925,5830 2047.5,5952.5 2047.5,5997.6 2030,6015.1 2030,6125 2045,6140 v1(2250.1,6140) v1@2250.1,6130.1
PIGND: C52.2 P6.14 P11.6 P11.9 P11.14 P11.20 P11.25 P11.30 P11.39 P14.1 PI_CTRL.7 | length 6421.1
  Top Layer w15: PI_CTRL.7 1020,5385 PI_CTRL.7@1030,5375 ; P11.9 1210,6185 P11.9@1225,6185 ; P11.30@1295,5180 1250,5225 1250,5335 ; 1395,5335 1250,5335 ; 1395,5435 1250,5435 P11.25 1250,5335
  Top Layer w20: 1100,6170 1100,6070 1135.47,6034.53 1250,6034.53 1250,6145 P11.9@1210,6185 ; 1100,6195 1100,6310 1125,6335 1250,6335 1250,6210 P11.9@1225,6185
  Top Layer w30: 1247.74,6037.26 P11.14 ; 1250,6335 P11.6
  Top Layer w40: P11.30 1355,5185 1395,5225 1395,5335 1395,5685 ; P11.20 1395,5685 ; P11.14 1385,5985 ; P11.6@1315,6395 1500,6395 P6.14 ; 1395,6380 1395,5685
  Top Layer w60: PI_CTRL.7 985,5390 945,5430 945,6120 1010,6185 P11.9
  Top Layer w70: PI_CTRL.7@1020,5385 P11.25 ; PI_CTRL.7@1030,5375 1030,4745 1090,4685 P11.39
  Bottom Layer w70: P11.39 1190,4675 1190,4330 1240,4280 1505,4280 1551.1,4233.9 1551.1,4135 P14.1@1551.1,3938.15
R+: C33.1 P3.2 R29.2 U8.6 | length 2142.8
  Top Layer w15: v1(2980,4595) 2980,4325 3035,4270 U8.6 3165,4270 C33.1 ; v1(3160,4610) 3240,4690 R29.2
  Bottom Layer w15: P3.2 2620,5560 2685,5495 2685,5247.5 ; 2687.5,5247.5 2750,5185 2870,5185 2885,5170 2885,4765 2980,4670 2980,4620 ; v1(2980,4595) 3145,4595 v1(3160,4610)
R-: C43.1 P3.4 R37.2 U8.2 | length 1681.3
  Top Layer w15: v1@2645,4575 2710,4575 2720,4585 R37.2@2740,4585 ; C43.1 2735,4245 2810,4320 U8.2
  Bottom Layer w15: P3.4 2625,5460 2650,5435 2650,4300 C43.1
  other v1: 2645,4580
RST: C34.1 R28.2 U5.14 | length 1276.3
  Top Layer w15: U5.14 2172.68,5972.32 2230,5915 2230,5699.67 2254.31,5675.36 2254.31,5264.98 2254.31,5200.69 2295,5160 R28.2 ; v1(2480,4920) 2485,4915 C34.1
  Bottom Layer w15: v1(2300,5100) 2340,5060 2410,5060 2480,4990 v1(2480,4920)
S0: P7.1 R34.2 U7.6 | length 1481.4
  Top Layer w15: U7.6 2075,5575 2100,5600 2185,5600 2195,5590 2195,5578.46 2204.31,5569.15 2204.31,5448.96 2190,5434.64 2190,5004.64 2185,4999.64 2185,4920 2132.5,4867.5 2132.5,4727.5 2165,4695 R34.2 2210,4735 2235,4760 v1(2235,4765)
  Bottom Layer w15: P7.1 v1(2235,4765)
S1: P7.3 R33.2 U7.1 | length 1241.3
  Top Layer w15: v1(2175,4770) 2175,4800 2210,4835 R33.2 2210,4989.29 2215,4994.29 2215,5424.29 2229.31,5438.6 2229.31,5640.69 2175.51,5694.49 2175.51,5714.49 U7.1
  Bottom Layer w15: P7.3 2135,4720 2175,4760 v1(2175,4770)
SCLKPI: P11.23 PI_CTRL.6 | length 187.1
  Top Layer w15: PI_CTRL.6 1020,5485 P11.23
SCLPI: P11.5 PI_CTRL.1 | length 553.1
  Top Layer w15: v1(1005,6315) 1075,6385 P11.5
  Bottom Layer w15: v1(1005,6315) 1005,6000 PI_CTRL.1
SDAPI: P11.3 PI_CTRL.2 | length 847.2
  Top Layer w15: v1(950,6365) 950,6375 1060,6485 P11.3
  Bottom Layer w15: v1(950,6365) 950,5942.18 933.91,5926.09 970,5890 PI_CTRL.2
VCOML: C18.2 C21.2 U5.22 | length 1413.1
  Top Layer w15: U5.22 2520.49,6151.46 ; v1(3440,5960) v1@3442.64,5962.64
  Top Layer w20: 2520.49,6151.46 2571.94,6100 2645,6100 v1(2660,6085)
  Top Layer w30: v1@3442.64,5962.64 3540,5962.64 3577.36,6000 C18.2
  Bottom Layer w15: v1(2660,6085) v1@2665,6090
  Bottom Layer w30: v1@2665,6090 3310,6090 v1(3440,5960)
VCOMR: C17.2 C20.2 U5.21 | length 912.1
  Top Layer w15: U5.21 2499.13,6125.87 ; v1(3020,6000) v1@3022.36,5997.64 ; C20.2@3105,5997.64 C20.2@3107.36,6000
  Top Layer w20: 2499.13,6125.87 2562.5,6062.5 2588.46,6062.5 2610.96,6040 v1(2725,6040)
  Top Layer w30: v1@3022.36,5997.64 C20.2@3105,5997.64 ; C20.2@3107.36,6000 C17.2@3315,6000
  Bottom Layer w25: v1(2725,6040) 2870,6040
  Bottom Layer w30: 2870,6040 2910,6000 v1(3020,6000)
ZERO: R27.1 U5.13 | length 1268.4
  Top Layer w15: U5.13 2192.09,5997.91 2255,5935 2255,5710.02 2279.31,5685.71 2279.31,5265.69 2350,5195 R27.1@2350,4830
pads on no net: P11.7 P11.8 P11.10 P11.11 P11.13 P11.16 P11.17 P11.18 P11.22 P11.24 P11.26 P11.27 P11.28 P11.29 P11.31 P11.32 P11.33 P11.34 P11.36 P11.37 P11.38 U1.0 U2.0 U3.0 U6.1 U6.5 U6.8 U7.7 U9.3 U10.1 U10.5 U10.8 U11.3
copper on no net:
  other v2: 960,3790 5155,3795 950,6675 5155,6675

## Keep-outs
Keep-Out Layer:
  lines w7.87: 860,3690 5255,3690 5260,3695 5260,6780 860,6780 860,3730 860,3690

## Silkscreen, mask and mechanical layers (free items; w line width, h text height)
Top Overlay:
  lines w7.87: 1560,3805 1560,3825 ; 1815,3795 1815,3820 ; 2015,3810 2015,3820 ; 5105,4650 5135,4650 ; 5105,5330 5140,5330 ; 5105,5625 5140,5625 ; 5110,4835 5180,4835 5180,4860 ; 5110,5150 5175,5150 5180,5145 5180,5115 ; 5110,5835 5145,5835 ; 5120,3825 5125,3830
  text "Raspberry PI I2S DAC" at 2975,5835 h60
  text "+VAD" at 5215,5745 h60 r90
  text "Tomasz Jablonski 2020" at 2930,5735 h60
  text "AGND" at 5215,5500 h60 r90
  text "+VA" at 5210,5245 h60 r90
  text "AGND" at 5210,4880 h60 r90
  text "-VA" at 5210,4545 h60 r90
  text "F0" at 1445,4350 h60
  text "F1" at 1600,4350 h60
  text "+5VPI" at 1185,3730 h60
  text "PIGN" at 1475,3730 h60
  text "DGND" at 1710,3730 h60
  text "+VDD" at 1945,3730 h60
